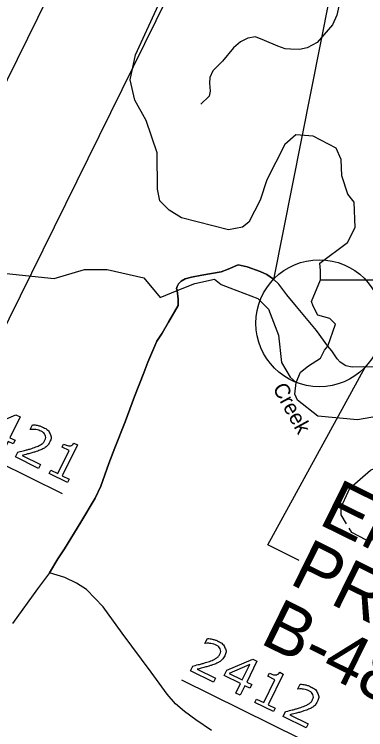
# Model space of a CAD drawing. Extents: x 1428428 to 1430511, y 857911 to 859585.
# Drawn here: x 1429036.9 to 1429106.2, y 859309.5 to 859450.7 of the extents above; entities that cross this region are included whole.
import ezdxf

# ---------------------------------------------------------------- set-up
doc = ezdxf.new("R2010")
doc.units = 0
for name, color, linetype in [('Default', 7, 'Continuous'), ('Exist Hydrographic Creek Single Shore', 7, 'Continuous'), ('Exist Hydrographic Creek Single Shore Label', 7, 'Continuous'), ('Exist Hydrographic Misc Water Feature', 7, 'Continuous'), ('Exist Road Non-System Type 51', 7, 'Continuous'), ('Exist Road Secondary Type 51 Attributed', 7, 'Continuous'), ('Scratch_Level_3', 7, 'Continuous'), ('Sheet Title CELL', 7, 'Continuous')]:
    doc.layers.add(name, color=color, linetype=linetype)

msp = doc.modelspace()

# ---------------------------------------------------------------- linework, layer by layer
at = {"layer": 'Default'}
for p, q in [((1429103.82, 859477.64), (1429088.02, 859398.35)), ((1429086.93, 859345.92), (1429106.15, 859381.05)), ((1429023.13, 859367.5), (1429046.33, 859356.08)), ((1429093.12, 859342.87), (1429086.93, 859345.92)), ((1429069.85, 859319.28), (1429093.43, 859307.68))]:
    msp.add_line(p, q, dxfattribs=at)
for points in [[(1429036.66, 859365.87), (1429035.66, 859366.36), (1429034.73, 859364.47), (1429033.86, 859364.89), (1429034.79, 859366.79), (1429031.57, 859368.38), (1429032.08, 859369.42), (1429037.21, 859371.61), (1429038.04, 859371.2), (1429036.02, 859367.09), (1429037.02, 859366.6), (1429036.66, 859365.87)], [(1429040.03, 859368.69), (1429039.99, 859368.72), (1429040.45, 859369.66)], [(1429047.39, 859358.24), (1429043.74, 859360.03), (1429044.08, 859360.72), (1429045.48, 859360.03), (1429047.7, 859364.54), (1429046.3, 859365.23), (1429046.6, 859365.84)], [(1429048.63, 859366.01), (1429049.34, 859365.67), (1429046.35, 859359.6), (1429047.72, 859358.92), (1429047.39, 859358.24)], [(1429041.67, 859361.05), (1429037.11, 859363.29), (1429037.58, 859364.25)], [(1429038.43, 859363.61), (1429042.06, 859361.83), (1429041.67, 859361.05)], [(1429074.55, 859326.48), (1429074.51, 859326.5), (1429074.98, 859327.45)], [(1429083.38, 859317.65), (1429082.38, 859318.14), (1429081.45, 859316.25), (1429080.58, 859316.67), (1429081.51, 859318.57), (1429078.29, 859320.16), (1429078.8, 859321.2), (1429083.93, 859323.39), (1429084.76, 859322.98), (1429082.74, 859318.87), (1429083.74, 859318.38), (1429083.38, 859317.65)], [(1429076.2, 859318.83), (1429071.64, 859321.08), (1429072.1, 859322.03)], [(1429072.96, 859321.39), (1429076.58, 859319.61), (1429076.2, 859318.83)], [(1429081.87, 859319.29), (1429083.37, 859322.33), (1429079.26, 859320.58), (1429081.87, 859319.29)], [(1429088.01, 859313.02), (1429084.37, 859314.81), (1429084.7, 859315.5), (1429086.11, 859314.81), (1429088.32, 859319.32), (1429086.92, 859320.01), (1429087.23, 859320.62)], [(1429089.26, 859320.79), (1429089.96, 859320.45), (1429086.97, 859314.38), (1429088.35, 859313.71), (1429088.01, 859313.02)], [(1429092.85, 859317.47), (1429092.81, 859317.5), (1429093.27, 859318.44)], [(1429094.49, 859309.83), (1429089.93, 859312.07), (1429090.4, 859313.02)], [(1429091.25, 859312.39), (1429094.88, 859310.61), (1429094.49, 859309.83)]]:
    msp.add_lwpolyline(points, dxfattribs=at)
for points in [[(1429040.45, 859369.66), (1429040.85, 859369.66), (1429041.45, 859369.53), (1429042.05, 859369.4), (1429042.56, 859369.15), (1429043.59, 859368.64), (1429043.93, 859367.85), (1429044.28, 859367.06), (1429043.86, 859366.21), (1429043.67, 859365.83), (1429043.41, 859365.54), (1429043.15, 859365.26), (1429042.81, 859365.05), (1429042.5, 859364.86), (1429042.13, 859364.71), (1429041.76, 859364.55), (1429041.25, 859364.39), (1429040.54, 859364.15), (1429039.8, 859363.96), (1429039.07, 859363.77), (1429038.43, 859363.61)], [(1429037.58, 859364.25), (1429038.26, 859364.42), (1429038.94, 859364.59), (1429039.61, 859364.76), (1429040.22, 859364.96), (1429041.51, 859365.37), (1429042.07, 859365.71), (1429042.64, 859366.04), (1429042.92, 859366.62), (1429043.18, 859367.14), (1429042.97, 859367.61), (1429042.77, 859368.08), (1429042.15, 859368.38), (1429041.74, 859368.58), (1429041.19, 859368.68), (1429040.64, 859368.77), (1429040.03, 859368.69)], [(1429046.6, 859365.84), (1429046.89, 859365.7), (1429047.24, 859365.59), (1429047.59, 859365.48), (1429047.8, 859365.48), (1429048.06, 859365.5), (1429048.27, 859365.61), (1429048.47, 859365.73), (1429048.63, 859366.01)], [(1429074.98, 859327.45), (1429075.37, 859327.45), (1429075.98, 859327.31), (1429076.58, 859327.18), (1429077.08, 859326.93), (1429078.11, 859326.42), (1429078.46, 859325.63), (1429078.8, 859324.85), (1429078.38, 859323.99), (1429078.19, 859323.61), (1429077.93, 859323.32), (1429077.67, 859323.04), (1429077.33, 859322.84), (1429077.02, 859322.64), (1429076.65, 859322.49), (1429076.28, 859322.33), (1429075.78, 859322.17), (1429075.06, 859321.94), (1429074.32, 859321.74), (1429073.59, 859321.55), (1429072.96, 859321.39)], [(1429072.1, 859322.03), (1429072.78, 859322.2), (1429073.46, 859322.37), (1429074.14, 859322.54), (1429074.75, 859322.74), (1429076.03, 859323.15), (1429076.59, 859323.49), (1429077.16, 859323.83), (1429077.44, 859324.4), (1429077.7, 859324.92), (1429077.5, 859325.39), (1429077.3, 859325.86), (1429076.68, 859326.16), (1429076.26, 859326.37), (1429075.71, 859326.46), (1429075.16, 859326.55), (1429074.55, 859326.48)], [(1429087.23, 859320.62), (1429087.51, 859320.48), (1429087.86, 859320.37), (1429088.21, 859320.26), (1429088.42, 859320.27), (1429088.68, 859320.28), (1429088.89, 859320.39), (1429089.09, 859320.51), (1429089.26, 859320.79)], [(1429090.4, 859313.02), (1429091.08, 859313.2), (1429091.75, 859313.37), (1429092.43, 859313.54), (1429093.04, 859313.74), (1429094.33, 859314.15), (1429094.89, 859314.49), (1429095.46, 859314.82), (1429095.74, 859315.4), (1429096, 859315.92), (1429095.79, 859316.39), (1429095.59, 859316.85), (1429094.97, 859317.16), (1429094.56, 859317.36), (1429094.01, 859317.45), (1429093.46, 859317.55), (1429092.85, 859317.47)], [(1429093.27, 859318.44), (1429093.67, 859318.44), (1429094.27, 859318.31), (1429094.87, 859318.18), (1429095.37, 859317.93), (1429096.41, 859317.42), (1429096.75, 859316.63), (1429097.1, 859315.84), (1429096.68, 859314.99), (1429096.49, 859314.61), (1429096.23, 859314.32), (1429095.97, 859314.04), (1429095.63, 859313.83), (1429095.32, 859313.64), (1429094.95, 859313.49), (1429094.57, 859313.33), (1429094.07, 859313.17), (1429093.36, 859312.93), (1429092.62, 859312.74), (1429091.89, 859312.55), (1429091.25, 859312.39)]]:
    msp.add_open_spline(points, degree=3, dxfattribs=at)
at = {"layer": 'Exist Hydrographic Creek Single Shore'}
for points in [[(1429097.34, 859398.23), (1429097.28, 859400.12), (1429097.16, 859401.52), (1429102.65, 859405.63), (1429104.18, 859408.6), (1429103.95, 859413.61), (1429102.68, 859415.15), (1429101.54, 859418.77), (1429101.36, 859422.04), (1429100.43, 859424.22), (1429095.83, 859426.6), (1429092.42, 859426.88), (1429090.29, 859424.95), (1429086.7, 859418.02), (1429085.38, 859413.97), (1429083.15, 859409.66), (1429081.89, 859408.68), (1429079.18, 859408.16), (1429069.89, 859410.53), (1429067.47, 859412), (1429065.6, 859413.86), (1429065.11, 859416.18), (1429065.08, 859423.36), (1429062.93, 859429.73), (1429060.65, 859433.71), (1429059.74, 859437.73), (1429060.78, 859442.66), (1429065.69, 859453.28)], [(1429098.76, 859385.16), (1429100.24, 859389.53), (1429099.18, 859390.65), (1429096.78, 859391.28), (1429095.85, 859393.04), (1429095.56, 859393.99), (1429097.34, 859398.23)], [(1429065.68, 859394.74), (1429069.01, 859396.14)], [(1429092.49, 859378), (1429093.34, 859380.05), (1429094.93, 859381.29), (1429097.32, 859382.78), (1429098.12, 859384.36), (1429098.76, 859385.16)], [(1429102.76, 859356.39), (1429103.11, 859357.13), (1429107.2, 859360.7), (1429114.54, 859364), (1429116.13, 859365.25), (1429116.73, 859366.42), (1429116.63, 859368.39), (1429115.75, 859370.32), (1429112.48, 859372.01), (1429104.63, 859370.61), (1429096.75, 859371.35), (1429092.76, 859374.53), (1429092.24, 859375.69), (1429092.49, 859378)], [(1429132.07, 859331.8), (1429128.82, 859329.84), (1429123.64, 859329.69), (1429121.97, 859331.85), (1429122.53, 859336.22), (1429121.68, 859338.58), (1429119.32, 859342.02), (1429118.4, 859345.67), (1429116.03, 859346.53), (1429106.28, 859346.91), (1429103.48, 859348.37), (1429102.94, 859349.26)]]:
    msp.add_lwpolyline(points, dxfattribs=at)
at = {"layer": 'Exist Hydrographic Misc Water Feature'}
for points in [[(1429097.34, 859398.23), (1429113.3, 859398.27), (1429116.3, 859400.49), (1429118.07, 859405.34), (1429117.98, 859414.26), (1429118.45, 859417.71), (1429121.28, 859423.19), (1429128.2, 859427.52), (1429130.78, 859430.32), (1429134.86, 859438.19), (1429136.92, 859448.36), (1429136.23, 859470.29), (1429135.95, 859472.66)], [(1429029.28, 859396.95), (1429031.16, 859398.05), (1429035.32, 859399.52), (1429044.76, 859398.55), (1429050.74, 859400.33), (1429055.23, 859400.3), (1429062.43, 859398.64), (1429065.68, 859394.74)], [(1429079.43, 859396.66), (1429084.92, 859394.55), (1429087.03, 859392.5), (1429089.05, 859387.31), (1429089.64, 859381.91), (1429091.35, 859379.03), (1429092.49, 859378)], [(1429102.44, 859350.1), (1429101.36, 859351.9), (1429101.37, 859353.37), (1429102.76, 859356.39)]]:
    msp.add_lwpolyline(points, dxfattribs=at)
at = {"layer": 'Exist Road Non-System Type 51'}
msp.add_lwpolyline([(1429101.61, 859455.35), (1429100.56, 859450.52), (1429099.68, 859448.6), (1429097.96, 859446.65), (1429096.62, 859445.09), (1429094.66, 859444.08), (1429093.16, 859443.74), (1429091.4, 859443.78), (1429090.31, 859443.87), (1429088.9, 859444.37), (1429086.27, 859445.48), (1429084.48, 859446.23), (1429082.95, 859445.97), (1429081.53, 859445.27), (1429080.11, 859444.06), (1429078, 859441.43), (1429076.05, 859439.53), (1429075.44, 859438.18), (1429075.42, 859437.11), (1429075.53, 859435.53), (1429075.36, 859434.53), (1429073.69, 859432.94)], dxfattribs=at)
at = {"layer": 'Exist Road Secondary Type 51 Attributed'}
for points in [[(1429081.09, 859401.24), (1429079.11, 859400.37), (1429077.68, 859399.82), (1429073.91, 859399.17), (1429071.86, 859398.78), (1429070.58, 859398.43), (1429069.82, 859397.98), (1429069.26, 859397.47), (1429068.99, 859396.93), (1429068.92, 859396.54), (1429069.01, 859396.14)], [(1429090.68, 859395.31), (1429089.1, 859397.38), (1429088.01, 859398.37), (1429086.74, 859399.29), (1429085.39, 859399.91), (1429082.83, 859400.8), (1429081.09, 859401.24)], [(1429069.01, 859396.14), (1429072.54, 859397.53), (1429076.36, 859398.39), (1429077.7, 859397.32), (1429079.43, 859396.66)], [(1429069.01, 859396.14), (1429069.2, 859394.45), (1429069.22, 859393.2), (1429067.32, 859389.91), (1429066.07, 859387.76), (1429064.98, 859386.13), (1429063.24, 859382), (1429062.42, 859379.89), (1429060.59, 859375.26), (1429058.79, 859370.24), (1429056.7, 859365.08), (1429055.54, 859362.01), (1429053.96, 859357.56), (1429052.82, 859355.15), (1429050.01, 859350.42), (1429046.78, 859345.13), (1429045.49, 859343.19), (1429043.85, 859340.44)], [(1429098.76, 859385.16), (1429096.53, 859388.26), (1429092.59, 859392.98), (1429090.68, 859395.31)], [(1429108.4, 859380.99), (1429105.74, 859381.06), (1429103.58, 859381.03), (1429102.29, 859381.3), (1429101.17, 859381.98), (1429100.57, 859382.65), (1429099.53, 859384.23), (1429098.76, 859385.16)], [(1429043.85, 859340.44), (1429041.48, 859337.27), (1429036.53, 859330.44)], [(1429075.8, 859309.33), (1429072.69, 859311.42), (1429070.45, 859313.04), (1429068.71, 859314.54), (1429067.07, 859316.45), (1429063.92, 859320.84), (1429058.17, 859328.54), (1429054.43, 859333.7), (1429051.12, 859337.12), (1429049.17, 859338.39), (1429046.82, 859339.48), (1429043.85, 859340.44)]]:
    msp.add_lwpolyline(points, dxfattribs=at)
at = {"layer": 'Scratch_Level_3'}
msp.add_line((1429096.55, 859514.03), (1428739.64, 858788.69), dxfattribs=at)
at = {"layer": 'Sheet Title CELL'}
msp.add_line((1428950.38, 859264.79), (1429091.66, 859551.91), dxfattribs=at)
for points in [[(1429069.01, 859396.14), (1429068.92, 859396.54), (1429068.99, 859396.93), (1429069.26, 859397.47), (1429069.82, 859397.98), (1429070.58, 859398.43), (1429071.86, 859398.78), (1429073.91, 859399.17), (1429077.68, 859399.82), (1429079.11, 859400.37), (1429081.09, 859401.24)], [(1429081.09, 859401.24), (1429082.83, 859400.8), (1429085.39, 859399.91), (1429086.74, 859399.29), (1429088.01, 859398.37), (1429088.02, 859398.35)], [(1429043.85, 859340.44), (1429045.49, 859343.19), (1429046.78, 859345.13), (1429050.01, 859350.42), (1429052.82, 859355.15), (1429053.96, 859357.56), (1429055.54, 859362.01), (1429056.7, 859365.08), (1429058.79, 859370.24), (1429060.59, 859375.26), (1429062.42, 859379.89), (1429063.24, 859382), (1429064.98, 859386.13), (1429066.07, 859387.76), (1429067.32, 859389.91), (1429069.22, 859393.2), (1429069.2, 859394.45), (1429069.01, 859396.14)], [(1429075.8, 859309.33), (1429072.69, 859311.42), (1429070.45, 859313.04), (1429068.71, 859314.54), (1429067.07, 859316.45), (1429063.92, 859320.84), (1429058.17, 859328.54), (1429054.43, 859333.7), (1429051.12, 859337.12), (1429049.17, 859338.39), (1429046.82, 859339.48), (1429043.85, 859340.44)]]:
    msp.add_lwpolyline(points, dxfattribs=at)
msp.add_circle((1429097.08, 859389.7), 12.53, dxfattribs=at)

# ---------------------------------------------------------------- texts
at = {"layer": 'Default'}
for s, p in [('END TIP', (1429096.7, 859350.15)), ('PROJECT', (1429090.91, 859338.39)), ('B-4846', (1429085.12, 859326.62))]:
    msp.add_text(s, height=10, rotation=333.8001, dxfattribs=at).set_placement(p)
at = {"layer": 'Exist Hydrographic Creek Single Shore Label'}
msp.add_text('Creek', height=3, rotation=298.6898, dxfattribs=at).set_placement((1429087.79, 859376.92))

doc.saveas('drawing.dxf')
